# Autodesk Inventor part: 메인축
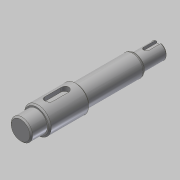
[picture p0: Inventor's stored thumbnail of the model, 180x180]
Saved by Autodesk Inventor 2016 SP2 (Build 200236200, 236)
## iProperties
Created: 2019-03
Part Number: 메인축
Material: 강철, 연강
Document SubType Name: Modeling
Designer: mduedu
Density: 1 g/cm^3
Appearance: 강철
Author: mduedu
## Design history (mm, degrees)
sketch "스케치1"
  geometry: L1 (0, 0)-(12, 0); L2 (12, 0)-(12, 8); L3 (12, 8)-(0, 8); L4 (0, 8)-(0, 0); L5 (12, 0)-(42, 0); L6 (42, 0)-(42, 10); L7 (42, 10)-(12, 10); L8 (12, 10)-(12, 0); L9 (42, 0)-(86, 0); L10 (86, 0)-(86, 8); L11 (86, 8)-(42, 8); L12 (42, 8)-(42, 0); L13 (86, 0)-(104, 0); L14 (104, 0)-(104, 6); L15 (104, 6)-(86, 6); L16 (86, 6)-(86, 0)
  constraints: 32 end point, 8 parallel, 4 horizontal, 4 perpendicular
  dimensions: "d0" = 16 diameter of L3 L1; "d2" = 20 diameter of L7 L5; "d3" = 16 diameter of L11 L9; "d4" = 12 diameter of L15 L13; "d5" = 12 distance of L2.end L3.end; "d6" = 30 distance of L6.end L7.end; "d7" = 86 distance between parallel lines of L10 L4; "d8" = 104 distance between parallel lines of L14 L4
revolve "회전1" sketch "스케치1" stored, may be unused: angle "d9" = 90 deg
node "작업 평면1"
sketch "스케치2" dims "d10" = 18
  geometry: L1 (6, -3)-(-6, -3); L2 (-6, -3)-(-6, 3); L3 (-6, 3)-(6, 3); L4 (6, 3)-(6, -3); L5 (15, 10)-(15, -10) reference; 3 further points
  constraints: 8 end point, 2 midpoint, 2 parallel, 2 vertical alignment, 1 horizontal, 1 horizontal alignment, 1 perpendicular, 4 other
  dimensions: "d12" = 6 distance between parallel lines of L3 L1; "d13" = 6 dimension on L5
extrude "돌출1" cut sketch "스케치2" distance "d14" = 3.5; taper "d15" = 0 deg
node "작업 평면2"
sketch "스케치3"
  geometry: L1 (-9, 6)-(-9, -6) reference; L2 (1, -2)-(-9, -2); L3 (1, 2)-(-9, 2); A1 r 2 centre (1, 0) between (1, -2) and (1, 2); 2 further points
  constraints: 4 end point, 2 point on circle, 2 point on line, 2 tangent, 1 centre point, 1 horizontal alignment, 1 midpoint, 1 parallel, 1 perpendicular
  dimensions: "d16" = 12 dimension on A1 L1; "d17" = 4 distance between parallel lines of L3 L2
extrude "돌출2" cut sketch "스케치3" distance "d18" = 2.5; taper "d19" = 0 deg
chamfer "모따기1" distance "d20" = 1; stored, may be unused: second distance "d21" = 2, angle "d22" = 45 deg
chamfer "모따기2" distance "d23" = 1; stored, may be unused: second distance "d24" = 2, angle "d25" = 45 deg
chamfer "모따기3" distance "d26" = 1.73; stored, may be unused: second distance "d27" = 2, angle "d28" = 30 deg
fillet "모깎기2" dims "d31" = 1, "d32" = 2
node "솔리드1"
